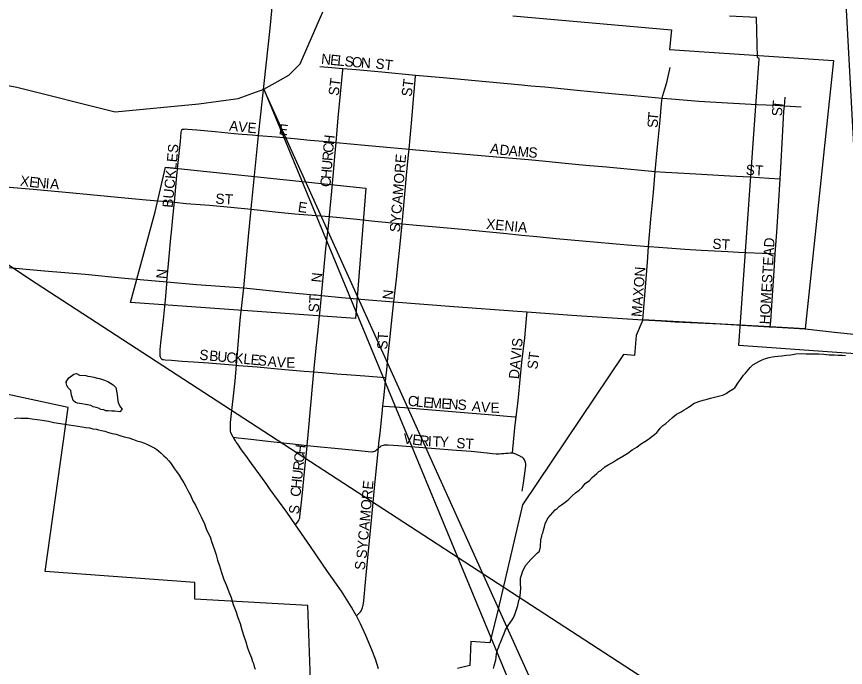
# Model space of a CAD drawing. Extents: x -5.4 to 49.9, y 13.2 to 48.4.
# Drawn here: x 29.333 to 30.099, y 43.289 to 43.891 of the extents above; entities that cross this region are included whole.
import ezdxf

# ---------------------------------------------------------------- set-up
doc = ezdxf.new("R2010")
doc.units = 0
for name, color, linetype in [('GM_X_City_Street', 7, 'Continuous'), ('GM_X_City_Street_Text', 7, 'Continuous'), ('GM_X_Corporation', 7, 'Continuous'), ('GM_X_Major_River', 7, 'Continuous'), ('GM_X_Minor_Lake', 7, 'Continuous'), ('GM_X_Minor_River', 7, 'Continuous'), ('GM_X_State_Route', 7, 'Continuous'), ('SH_Data', 7, 'Continuous')]:
    doc.layers.add(name, color=color, linetype=linetype)

msp = doc.modelspace()

# ---------------------------------------------------------------- linework, layer by layer
at = {"layer": 'GM_X_City_Street'}
for points in [[(29.61353, 43.84456), (29.62454, 43.84359), (29.63484, 43.84268)], [(29.62864, 43.77428), (29.63062, 43.79699), (29.63473, 43.84143), (29.63484, 43.84268)], [(29.63484, 43.84268), (29.64722, 43.8416), (29.67071, 43.8395), (29.70203, 43.83655)], [(29.69602, 43.76806), (29.6971, 43.77865), (29.69859, 43.79555), (29.70023, 43.81418), (29.70195, 43.83536), (29.70203, 43.83655)], [(29.70203, 43.83655), (29.72748, 43.83415), (29.76684, 43.83065), (29.80013, 43.82745), (29.80862, 43.82665), (29.8214, 43.82549), (29.84812, 43.82288), (29.86696, 43.82104), (29.88661, 43.8193), (29.90403, 43.81776), (29.92994, 43.81523)], [(29.92994, 43.81523), (29.93053, 43.81749), (29.93239, 43.82377), (29.93405, 43.82962), (29.93538, 43.83517), (29.93725, 43.84335)], [(29.92353, 43.74727), (29.92557, 43.77005), (29.92786, 43.79489), (29.92929, 43.81034), (29.92994, 43.81523)], [(29.92994, 43.81523), (29.93855, 43.81439), (29.96366, 43.81228), (29.99033, 43.81081), (30.01771, 43.8094), (30.03425, 43.80854), (30.04282, 43.8081)], [(30.04282, 43.8081), (30.04311, 43.81166), (30.04345, 43.81595)], [(30.03885, 43.74049), (30.03974, 43.75624), (30.04074, 43.77363), (30.04242, 43.80298), (30.04282, 43.8081)], [(30.04282, 43.8081), (30.05826, 43.8073)], [(29.47914, 43.71897), (29.47983, 43.7261), (29.48122, 43.74033), (29.48238, 43.75291), (29.48473, 43.77523), (29.48554, 43.7836), (29.48571, 43.78508), (29.48593, 43.7856), (29.48612, 43.78598), (29.48665, 43.78639), (29.48805, 43.78664), (29.48969, 43.78668), (29.49138, 43.78656), (29.49977, 43.78579), (29.51688, 43.78423), (29.53431, 43.78263), (29.54181, 43.78196), (29.55094, 43.78114), (29.55701, 43.7806)], [(29.55701, 43.7806), (29.57332, 43.77937), (29.58976, 43.77778), (29.6046, 43.77644), (29.62431, 43.77468), (29.62864, 43.77428)], [(29.6224, 43.70572), (29.62249, 43.70662), (29.6245, 43.72912), (29.62579, 43.74295), (29.62749, 43.76121), (29.62864, 43.77428)], [(29.62864, 43.77428), (29.65521, 43.7718), (29.66867, 43.77057), (29.69602, 43.76806)], [(29.68973, 43.69907), (29.69033, 43.70582), (29.69404, 43.74724), (29.69547, 43.76268), (29.69602, 43.76806)], [(29.69602, 43.76806), (29.7021, 43.76751), (29.73418, 43.76456), (29.78044, 43.76069), (29.80626, 43.75853), (29.82235, 43.75695), (29.84012, 43.75521), (29.85934, 43.75333), (29.87835, 43.75156), (29.89455, 43.75003), (29.90735, 43.74883), (29.92353, 43.74727)], [(29.91732, 43.67814), (29.91928, 43.70322), (29.92181, 43.72796), (29.92353, 43.74727)], [(29.92353, 43.74727), (29.93294, 43.74669), (29.95031, 43.74571), (29.96631, 43.74487), (29.99236, 43.74353), (30.01085, 43.74256), (30.02868, 43.7411), (30.03885, 43.74049)], [(29.24983, 43.73898), (29.27129, 43.73729), (29.28533, 43.73616), (29.30456, 43.73463), (29.34875, 43.7311), (29.38528, 43.72763), (29.43332, 43.72308), (29.45313, 43.7213), (29.47914, 43.71897)], [(30.03436, 43.67127), (30.03577, 43.69147), (30.03744, 43.71547), (30.03885, 43.74049)], [(29.47219, 43.64552), (29.47429, 43.66874), (29.47603, 43.68596), (29.47651, 43.69143), (29.4774, 43.70114), (29.47894, 43.71697), (29.47914, 43.71897)], [(29.47914, 43.71897), (29.49014, 43.71798), (29.51158, 43.71618), (29.53141, 43.71448), (29.55009, 43.71259)], [(29.55009, 43.71259), (29.57513, 43.70995), (29.59038, 43.70838), (29.59835, 43.70778), (29.6224, 43.70572)], [(29.61504, 43.63283), (29.61713, 43.65591), (29.61923, 43.67588), (29.62147, 43.69713), (29.6224, 43.70572)], [(29.6224, 43.70572), (29.63202, 43.70489), (29.64766, 43.70321), (29.66126, 43.70187), (29.68973, 43.69907)], [(29.68191, 43.62707), (29.68433, 43.64797), (29.6859, 43.6629), (29.68741, 43.67731), (29.68973, 43.69907)], [(29.68973, 43.69907), (29.7028, 43.69778), (29.72101, 43.69616), (29.74502, 43.69398), (29.76708, 43.69185), (29.78338, 43.69027), (29.8001, 43.68866), (29.81392, 43.68733), (29.83187, 43.6856), (29.85634, 43.68323), (29.89775, 43.67974), (29.91732, 43.67814)], [(29.91204, 43.61041), (29.91277, 43.62148), (29.91618, 43.6636), (29.91732, 43.67814)], [(29.91732, 43.67814), (29.91816, 43.67808), (29.93487, 43.67674), (29.95094, 43.67554), (29.96578, 43.67476), (29.99055, 43.67359), (30.00046, 43.67291), (30.02961, 43.6715), (30.03436, 43.67127)], [(30.0298, 43.60387), (30.03015, 43.60901), (30.03213, 43.63737), (30.03327, 43.65559), (30.03436, 43.67127)], [(29.24355, 43.66654), (29.26162, 43.66485), (29.28321, 43.66283), (29.32215, 43.65912), (29.35921, 43.65567), (29.39677, 43.65238), (29.43323, 43.64891), (29.47219, 43.64552)], [(29.47219, 43.64552), (29.47197, 43.6434), (29.4705, 43.62891), (29.46866, 43.61026), (29.46727, 43.59712), (29.46643, 43.58911), (29.46586, 43.58293), (29.46562, 43.57859), (29.4657, 43.57718), (29.46587, 43.57623), (29.46628, 43.57541), (29.46677, 43.5748), (29.46739, 43.57422), (29.46813, 43.57381), (29.46908, 43.57356), (29.47069, 43.57336), (29.47661, 43.57295), (29.48643, 43.57228), (29.49696, 43.57157), (29.51077, 43.57065), (29.53657, 43.56845)], [(29.47219, 43.64552), (29.49973, 43.64313), (29.54346, 43.63979)], [(29.60786, 43.56221), (29.60989, 43.58102), (29.61238, 43.60408), (29.61468, 43.629), (29.61504, 43.63283)], [(29.67462, 43.55688), (29.67545, 43.56392), (29.67651, 43.5751), (29.67813, 43.59176), (29.67962, 43.60707), (29.68162, 43.62456), (29.68191, 43.62707)], [(29.79501, 43.52071), (29.79608, 43.5303), (29.79698, 43.53855), (29.79869, 43.5552), (29.80033, 43.57123), (29.8029, 43.59382), (29.80479, 43.61503), (29.80502, 43.6176)], [(29.53657, 43.56845), (29.53841, 43.56829), (29.55574, 43.56697), (29.58129, 43.56456), (29.5992, 43.56289), (29.60786, 43.56221)], [(29.60186, 43.49432), (29.60302, 43.5076), (29.60696, 43.55224), (29.60786, 43.56221)], [(29.60786, 43.56221), (29.61569, 43.56158), (29.6293, 43.56049), (29.64261, 43.55943), (29.65505, 43.55844), (29.67378, 43.55696), (29.67462, 43.55688)], [(29.67177, 43.53081), (29.67256, 43.53839), (29.67348, 43.54728), (29.67462, 43.55688)], [(29.66767, 43.49172), (29.66813, 43.49641), (29.66916, 43.50566), (29.67103, 43.52365), (29.67177, 43.53081)], [(29.67177, 43.53081), (29.67334, 43.53068), (29.69179, 43.52918), (29.70969, 43.52772), (29.74316, 43.525), (29.76935, 43.5229), (29.79358, 43.52084), (29.79501, 43.52071)], [(29.79144, 43.48732), (29.79387, 43.51058), (29.79501, 43.52071)], [(29.53356, 43.50184), (29.53813, 43.5013), (29.54983, 43.49994), (29.56831, 43.49791), (29.58597, 43.49597), (29.60186, 43.49432)], [(29.59111, 43.42084), (29.5928, 43.42327), (29.59404, 43.42505), (29.59456, 43.42612), (29.59493, 43.42727), (29.59509, 43.4283), (29.59638, 43.43903), (29.5975, 43.45047), (29.59942, 43.46984), (29.60178, 43.49353), (29.60186, 43.49432)], [(29.60186, 43.49432), (29.61411, 43.49312), (29.62732, 43.49182), (29.64646, 43.48994), (29.66132, 43.4885), (29.66241, 43.48856), (29.66359, 43.48878), (29.6645, 43.48905), (29.66535, 43.48962), (29.66622, 43.49041), (29.66767, 43.49171), (29.66767, 43.49172)], [(29.66767, 43.49172), (29.66874, 43.49259), (29.6695, 43.49332), (29.67025, 43.49393), (29.67111, 43.49429), (29.67231, 43.49459), (29.67334, 43.49471), (29.67425, 43.49477), (29.67534, 43.49477), (29.67661, 43.49474), (29.68596, 43.4941), (29.71276, 43.49206), (29.73988, 43.49), (29.7535, 43.48883), (29.76831, 43.48732), (29.77324, 43.48681), (29.77645, 43.48664), (29.77938, 43.48655), (29.78149, 43.48668), (29.78369, 43.48675), (29.78556, 43.48699), (29.78768, 43.48717), (29.78947, 43.48732), (29.79144, 43.48732)], [(29.64728, 43.33694), (29.64876, 43.33814), (29.65034, 43.33948), (29.65124, 43.34059), (29.6518, 43.34146), (29.65242, 43.34265), (29.65275, 43.34351), (29.65308, 43.34441), (29.65332, 43.34564), (29.65353, 43.3468), (29.65383, 43.3486), (29.65411, 43.35078), (29.6559, 43.3678), (29.65772, 43.38738), (29.65946, 43.40615), (29.66165, 43.42841), (29.66442, 43.45809), (29.66767, 43.49172)], [(29.80056, 43.45193), (29.80168, 43.45948), (29.80329, 43.47073), (29.80362, 43.47368), (29.80377, 43.47501), (29.80384, 43.47632), (29.80388, 43.47734), (29.80363, 43.47853), (29.80339, 43.47932), (29.80296, 43.48025), (29.80252, 43.48098), (29.80189, 43.48177), (29.801, 43.48269), (29.80006, 43.48338), (29.79936, 43.48383), (29.79854, 43.48428), (29.79637, 43.48539), (29.79459, 43.48619), (29.79284, 43.48687), (29.79144, 43.48732)]]:
    msp.add_lwpolyline(points, dxfattribs=at)
at = {"layer": 'GM_X_Corporation'}
for points in [[(30.0978, 43.93683), (30.11717, 43.57845), (30.00085, 43.58666), (30.01955, 43.85142), (30.01808, 43.85261), (30.01694, 43.88966), (29.99211, 43.89093)], [(29.28308, 43.68973), (29.34531, 43.6481), (30.11202, 43.14996), (30.11178, 43.12523), (30.14245, 43.10478), (30.18213, 43.0705), (30.20678, 43.03863), (30.22422, 43.00735), (30.23805, 42.97187), (30.24767, 42.96585), (30.20088, 43.89052), (30.17852, 43.90074)], [(29.79173, 43.89119), (29.93862, 43.8783), (29.93676, 43.86015), (30.08829, 43.85), (30.06198, 43.60198), (30.0298, 43.60387), (29.91204, 43.61041), (29.90576, 43.59589), (29.90424, 43.57749), (29.89398, 43.5783), (29.80092, 43.43935), (29.77834, 43.34299), (29.77049, 43.31191), (29.75316, 43.31301), (29.75207, 43.29087), (29.74064, 43.28811)], [(29.46127, 43.71025), (29.46623, 43.7314), (29.47091, 43.75139), (29.65598, 43.73201), (29.64659, 43.61166), (29.43873, 43.62633), (29.46127, 43.71025)], [(29.60533, 43.26873), (29.60231, 43.34636), (29.49793, 43.35219), (29.49792, 43.36751), (29.35982, 43.37768), (29.38093, 43.52938), (29.17703, 43.57322)]]:
    msp.add_lwpolyline(points, dxfattribs=at)
at = {"layer": 'GM_X_Major_River'}
msp.add_lwpolyline([(29.27405, 43.83664), (29.33359, 43.82519), (29.42431, 43.80247), (29.50164, 43.81001), (29.53806, 43.81497), (29.56168, 43.8236), (29.58502, 43.83641), (29.59544, 43.84683), (29.61646, 43.89499)], dxfattribs=at)
at = {"layer": 'GM_X_Minor_Lake'}
msp.add_lwpolyline([(29.3793, 43.55295), (29.38162, 43.55672), (29.38621, 43.56009), (29.38887, 43.56082), (29.39151, 43.55927), (29.3972, 43.55883), (29.39909, 43.55843), (29.40174, 43.55802), (29.40477, 43.55722), (29.40817, 43.55642), (29.41007, 43.55602), (29.41196, 43.55562), (29.4146, 43.55445), (29.41763, 43.55328), (29.42027, 43.55173), (29.42253, 43.55018), (29.42516, 43.54787), (29.42623, 43.5414), (29.42657, 43.53798), (29.42728, 43.53379), (29.42952, 43.52959), (29.43101, 43.52767), (29.42871, 43.52542), (29.42416, 43.52585), (29.42151, 43.52588), (29.4181, 43.5263), (29.41582, 43.52632), (29.41393, 43.5271), (29.41128, 43.52751), (29.40902, 43.52868), (29.40675, 43.52946), (29.4041, 43.52987), (29.40183, 43.53104), (29.39881, 43.53183), (29.39691, 43.53223), (29.3935, 43.53265), (29.39161, 43.53305), (29.38972, 43.53345), (29.38782, 43.53386), (29.38557, 43.53578), (29.38484, 43.53883), (29.3841, 43.54074), (29.38339, 43.54492), (29.38114, 43.54761), (29.37964, 43.54953), (29.37929, 43.55219), (29.3793, 43.55295), (29.37929, 43.55257)], dxfattribs=at)
at = {"layer": 'GM_X_Minor_River'}
for points in [[(30.00849, 43.56297), (30.01119, 43.56636), (30.01349, 43.56861), (30.01921, 43.57197), (30.02227, 43.57345), (30.02531, 43.57456), (30.02874, 43.57566), (30.0314, 43.57601), (30.03406, 43.57636), (30.03672, 43.57671), (30.04052, 43.57705), (30.0447, 43.57776), (30.04888, 43.57809), (30.05343, 43.5788), (30.05875, 43.57912), (30.06292, 43.57907), (30.06672, 43.57903), (30.07051, 43.57899), (30.07468, 43.57894), (30.07923, 43.57851), (30.08416, 43.57808), (30.08871, 43.57802), (30.0925, 43.5776), (30.09592, 43.57756), (30.09933, 43.57752)], [(29.77652, 43.29847), (29.77693, 43.30189), (29.77773, 43.3053), (29.7789, 43.30832), (29.77968, 43.31021), (29.78046, 43.3121), (29.78163, 43.31513), (29.78279, 43.31778), (29.78396, 43.32042), (29.78513, 43.32383), (29.78745, 43.32798), (29.78976, 43.331), (29.7913, 43.33326), (29.79285, 43.33552), (29.79402, 43.33893), (29.7952, 43.34271), (29.79638, 43.3465), (29.79756, 43.35105), (29.79835, 43.35332), (29.79874, 43.35521), (29.7992, 43.36205), (29.79887, 43.36661), (29.79892, 43.37155), (29.8001, 43.37533), (29.80088, 43.37761), (29.80205, 43.38025), (29.80398, 43.38365), (29.80859, 43.38892), (29.81204, 43.3923), (29.81472, 43.39493), (29.81664, 43.39643), (29.81744, 43.40059), (29.81789, 43.40743), (29.81868, 43.41046), (29.81908, 43.41236), (29.81986, 43.41425), (29.82026, 43.41614), (29.82105, 43.41917), (29.82184, 43.42182), (29.82339, 43.42523), (29.82455, 43.42749), (29.83108, 43.43464), (29.83299, 43.43614), (29.83491, 43.43801), (29.83682, 43.43951), (29.83911, 43.44101), (29.84141, 43.44288), (29.84371, 43.44476), (29.84678, 43.44776), (29.84984, 43.45039), (29.85328, 43.45301), (29.85596, 43.45526), (29.85866, 43.45903), (29.86286, 43.46202), (29.86517, 43.46465), (29.86746, 43.46652), (29.86938, 43.4684), (29.8713, 43.47028), (29.8732, 43.47102), (29.87703, 43.4744), (29.88009, 43.47626), (29.88391, 43.4785), (29.88773, 43.48112), (29.89346, 43.48447), (29.89804, 43.48708), (29.90224, 43.49007), (29.90644, 43.49268), (29.90988, 43.4953), (29.91371, 43.49792), (29.91714, 43.50016), (29.92021, 43.50241), (29.92288, 43.50428), (29.9248, 43.50615), (29.92634, 43.50804), (29.92788, 43.5103), (29.93056, 43.51255), (29.93323, 43.51442), (29.93592, 43.51705), (29.93936, 43.52005), (29.94319, 43.52305), (29.94739, 43.52528), (29.95006, 43.52715), (29.95235, 43.52826), (29.95426, 43.52976), (29.95656, 43.53126), (29.95885, 43.53313), (29.96381, 43.53497), (29.96761, 43.53607), (29.97142, 43.53717), (29.97446, 43.53789), (29.98321, 43.54007), (29.98587, 43.5408), (29.98892, 43.54229), (29.9916, 43.54416), (29.99504, 43.5464), (29.99695, 43.54752), (30.00042, 43.5528), (30.00234, 43.55506), (30.00504, 43.55921), (30.00696, 43.56108), (30.00849, 43.56297)], [(29.33151, 43.51929), (29.33417, 43.51964), (29.33721, 43.51961), (29.34024, 43.51957), (29.34404, 43.51953), (29.34782, 43.51873), (29.35237, 43.5183), (29.35692, 43.51749), (29.36298, 43.51666), (29.3679, 43.51546), (29.38192, 43.5134), (29.38608, 43.5126), (29.38987, 43.51218), (29.39404, 43.51137), (29.39745, 43.51095), (29.40086, 43.51053), (29.40388, 43.50974), (29.40729, 43.50932), (29.40918, 43.50854), (29.41184, 43.50813), (29.41486, 43.50733), (29.41827, 43.50616), (29.42167, 43.50536), (29.42546, 43.50455), (29.42886, 43.50338), (29.43264, 43.5022), (29.43718, 43.50138), (29.44134, 43.49982), (29.44436, 43.49864), (29.44815, 43.49746), (29.45155, 43.49628), (29.45419, 43.49511), (29.45684, 43.49394), (29.4591, 43.49278), (29.46099, 43.49162), (29.46287, 43.49046), (29.46475, 43.48892), (29.46701, 43.48699), (29.46926, 43.48469), (29.47151, 43.48276), (29.47414, 43.48007), (29.47564, 43.47815), (29.47751, 43.47547), (29.47938, 43.47279), (29.48124, 43.47011), (29.48349, 43.46667), (29.48573, 43.46322), (29.48797, 43.45978), (29.48983, 43.45634), (29.49168, 43.45252), (29.49392, 43.44831), (29.49613, 43.44297), (29.49875, 43.43914), (29.5006, 43.43494), (29.50246, 43.4315), (29.50395, 43.42844), (29.50505, 43.42539), (29.50654, 43.42271), (29.50765, 43.42004), (29.50838, 43.41737), (29.51247, 43.40897), (29.51357, 43.40554), (29.51467, 43.4021), (29.51615, 43.39791), (29.51762, 43.39333)], [(29.51762, 43.39333), (29.51908, 43.38838), (29.52092, 43.38304), (29.52275, 43.37694), (29.52496, 43.37045), (29.52718, 43.36473), (29.52939, 43.35901), (29.53161, 43.35366), (29.53344, 43.34718), (29.53603, 43.34107), (29.53787, 43.33535), (29.54008, 43.32963), (29.54154, 43.32391), (29.54338, 43.31819), (29.54522, 43.31285), (29.54667, 43.30714), (29.54852, 43.30218), (29.55037, 43.29798), (29.55147, 43.29454), (29.55221, 43.29264), (29.55294, 43.28997), (29.55368, 43.28768)], [(29.77413, 43.28824), (29.77453, 43.29051), (29.77611, 43.29619), (29.77652, 43.29847)]]:
    msp.add_lwpolyline(points, dxfattribs=at)
at = {"layer": 'GM_X_State_Route'}
for points in [[(29.55041, 43.71654), (29.55062, 43.71914), (29.55439, 43.756), (29.55701, 43.7806), (29.56757, 43.87956), (29.56905, 43.89593), (29.56956, 43.90305), (29.56973, 43.90657), (29.56915, 43.9149), (29.56877, 43.918)], [(29.54346, 43.63979), (29.54764, 43.68747), (29.55009, 43.71259), (29.55041, 43.71654)], [(29.53114, 43.51537), (29.53536, 43.554), (29.53657, 43.56845), (29.54008, 43.61015), (29.54346, 43.63979)], [(29.54346, 43.63979), (29.58146, 43.63603), (29.60801, 43.63348), (29.61007, 43.63329)], [(29.61007, 43.63329), (29.61504, 43.63283), (29.63396, 43.63108), (29.65854, 43.62894), (29.68191, 43.62707), (29.7097, 43.62484)], [(29.7097, 43.62484), (29.73731, 43.62263), (29.79615, 43.61826), (29.80502, 43.6176), (29.8463, 43.6145), (29.91204, 43.61041)], [(29.91204, 43.61041), (29.929, 43.60938)], [(29.929, 43.60938), (29.94186, 43.60859), (29.94896, 43.60824)], [(29.94896, 43.60824), (29.98349, 43.60649), (30.0288, 43.60393)], [(30.0288, 43.60393), (30.0298, 43.60387), (30.0307, 43.60382), (30.06198, 43.60198), (30.0891, 43.59908), (30.15088, 43.59232), (30.18547, 43.58851), (30.21386, 43.58513), (30.23726, 43.58194), (30.24978, 43.58024), (30.25757, 43.57846), (30.26537, 43.57634), (30.27263, 43.57386), (30.27847, 43.57156), (30.28343, 43.56943), (30.28822, 43.56713), (30.29211, 43.56501)], [(29.66786, 43.28786), (29.66491, 43.29674), (29.66165, 43.3055), (29.65615, 43.31873), (29.65114, 43.32947), (29.64728, 43.33694), (29.64714, 43.33723), (29.64271, 43.34475), (29.63343, 43.35951), (29.62068, 43.3779), (29.605, 43.40103), (29.59111, 43.42084), (29.58292, 43.43254), (29.56769, 43.45368), (29.56453, 43.45823), (29.5606, 43.46373), (29.55819, 43.4671), (29.55055, 43.47752), (29.54508, 43.48494), (29.54116, 43.49034), (29.53764, 43.49533), (29.53631, 43.49738), (29.53563, 43.49839), (29.53372, 43.50154), (29.53356, 43.50184), (29.53227, 43.50422), (29.53136, 43.50637), (29.53109, 43.50738), (29.5309, 43.50895), (29.53093, 43.51131), (29.53104, 43.51449), (29.53114, 43.51537)]]:
    msp.add_lwpolyline(points, dxfattribs=at)
at = {"layer": 'SH_Data'}
msp.add_lwpolyline([(31.07294, 40.48034), (29.56168, 43.8236), (31.07294, 40.1733)], close=True, dxfattribs=at)

# ---------------------------------------------------------------- texts
at = {"layer": 'GM_X_City_Street_Text'}
for s, rotation, p in [('N', 354.30681, (29.61443, 43.84689)), ('E', 354.30843, (29.62272, 43.84606)), ('L', 354.28125, (29.62935, 43.8454)), ('S', 354.30067, (29.63599, 43.84473)), ('O', 355.13896, (29.64278, 43.84406)), ('N', 356.37821, (29.6513, 43.84334)), ('ST', 352.88003, (29.66447, 43.84272)), ('ST', 82.87834, (29.63081, 43.817)), ('ST', 82.87834, (29.69832, 43.81617)), ('S', 89.04378, (30.0408, 43.79841)), ('T', 84.28124, (30.0409, 43.80487)), ('T', 84.22688, (29.92592, 43.79403)), ('A', 353.62601, (29.52947, 43.78522)), ('V', 353.62601, (29.53775, 43.78429)), ('E', 355.41594, (29.54635, 43.78334)), ('E', 352.87835, (29.57531, 43.78188)), ('S', 88.8799, (29.9258, 43.78757)), ('H', 83.95667, (29.62647, 43.77173)), ('BUCKLES', 84.5223, (29.47747, 43.71357)), ('C', 85.35733, (29.62586, 43.76432)), ('A', 351.00124, (29.7704, 43.76437)), ('D', 354.03366, (29.77917, 43.76299)), ('A', 355.21825, (29.78767, 43.7621)), ('M', 355.25069, (29.79599, 43.76141)), ('S', 355.25333, (29.80595, 43.76058)), ('R', 85.36481, (29.62526, 43.75684)), ('SYCAMORE', 85.34804, (29.68747, 43.69098)), ('U', 85.36159, (29.62459, 43.74854)), ('ST', 356.42537, (30.00686, 43.74439)), ('H', 85.35314, (29.62391, 43.74023)), ('X', 352.50357, (29.33616, 43.73438)), ('E', 353.72633, (29.34464, 43.73327)), ('N', 355.35315, (29.35156, 43.73251)), ('I', 355.45042, (29.35988, 43.73183)), ('A', 355.48809, (29.36404, 43.7315)), ('C', 85.35733, (29.62331, 43.73275)), ('ST', 356.42537, (29.51686, 43.71772)), ('E', 351.87427, (29.59283, 43.71021)), ('XENIA', 354.61377, (29.76692, 43.69439)), ('ST', 356.42622, (29.97603, 43.67606)), ('HOMESTEAD', 86.67235, (30.02914, 43.60601)), ('N', 84.26992, (29.47164, 43.64779)), ('N', 84.29157, (29.61498, 43.64446)), ('MAXON', 85.59968, (29.91081, 43.61275)), ('N', 84.29372, (29.68081, 43.62862)), ('ST', 86.18785, (29.61247, 43.6169)), ('ST', 86.42621, (29.67581, 43.58272)), ('DAVIS', 84.56261, (29.79748, 43.55529)), ('S', 354.61018, (29.50192, 43.57356)), ('B', 354.60177, (29.51105, 43.5727)), ('U', 354.61561, (29.51851, 43.57199)), ('C', 354.60111, (29.52681, 43.57121)), ('K', 354.59824, (29.53428, 43.5705)), ('L', 354.60517, (29.54257, 43.56972)), ('E', 354.61018, (29.54921, 43.56909)), ('S', 354.61018, (29.55585, 43.56846)), ('A', 354.60876, (29.56498, 43.5676)), ('V', 355.71404, (29.57347, 43.5668)), ('ST', 82.88002, (29.81448, 43.56415)), ('E', 359.27948, (29.58243, 43.56615)), ('C', 354.04056, (29.69444, 43.53105)), ('L', 354.23686, (29.70194, 43.53027)), ('E', 355.55784, (29.70881, 43.52958)), ('M', 356.32683, (29.71559, 43.52905)), ('E', 356.33676, (29.72557, 43.52841)), ('N', 356.34482, (29.73223, 43.52798)), ('S', 356.34373, (29.74055, 43.52745)), ('A', 354.1111, (29.75361, 43.52605)), ('V', 355.42061, (29.76214, 43.52518)), ('E', 359.27948, (29.77114, 43.52448)), ('V', 353.71532, (29.69028, 43.49605)), ('E', 353.70505, (29.69857, 43.49514)), ('R', 354.38318, (29.70532, 43.49439)), ('I', 356.70543, (29.71319, 43.49363)), ('T', 357.57408, (29.71751, 43.49338)), ('Y', 357.68138, (29.72418, 43.4931)), ('ST', 356.42622, (29.73936, 43.49189)), ('H', 83.65033, (29.59972, 43.48547)), ('C', 83.64907, (29.59889, 43.47801)), ('R', 83.65489, (29.59806, 43.47056)), ('U', 83.64773, (29.59714, 43.46228)), ('H', 83.93494, (29.59626, 43.454)), ('SYCAMORE', 84.80505, (29.65664, 43.38942)), ('C', 86.37973, (29.5958, 43.44662)), ('S', 82.87834, (29.59415, 43.43034)), ('S', 82.87834, (29.65498, 43.37867))]:
    msp.add_text(s, height=0.00947, rotation=rotation, dxfattribs=at).set_placement(p)

doc.saveas('drawing.dxf')
